Omron CX-Programmer project NuevoProyecto (CX-Programmer 9.50)

# PLC NewPLC1: CP1L-E EM

## Program P15 (cyclic task 0)
Local symbols
E 0.10 BOOL  ; Pulsador de Emergencia
Em 15.01 BOOL  ; Emergencia memorizada
Etapa_0 10.00 BOOL
Etapa_1 10.01 BOOL
Etapa_10 10.10 BOOL
Etapa_11 10.11 BOOL
Etapa_12 10.12 BOOL
Etapa_2 10.02 BOOL
Etapa_20 10.13 BOOL
Etapa_21 10.14 BOOL
Etapa_3 10.03 BOOL
Etapa_30 10.15 BOOL
Etapa_31 11.00 BOOL
Etapa_4 10.04 BOOL
Etapa_40 11.01 BOOL
Etapa_41 11.02 BOOL
Etapa_5 10.05 BOOL
Etapa_50 11.03 BOOL
Etapa_51 11.04 BOOL
Etapa_6 10.06 BOOL
Etapa_7 10.07 BOOL
Etapa_8 10.08 BOOL
Etapa_9 10.09 BOOL
FBS5 15.00 BOOL  ; Flanco Bajada S5
FC1 0.06 BOOL
FC2 0.07 BOOL
FC3 0.08 BOOL
FC4 0.09 BOOL
KC1 100.00 BOOL
KC2 100.01 BOOL
KC3 100.02 BOOL
KCP 100.03 BOOL
KCS 100.04 BOOL
KPD 100.05 BOOL
KPI 100.06 BOOL
R 0.11 BOOL  ; Pulsador de Rearme
S_1 0.01 BOOL
S_2 0.02 BOOL
S_3 0.03 BOOL
S_4 0.04 BOOL
S_5 0.05 BOOL
m 0.00 BOOL

### Section Sección1_GRAFCET_principal

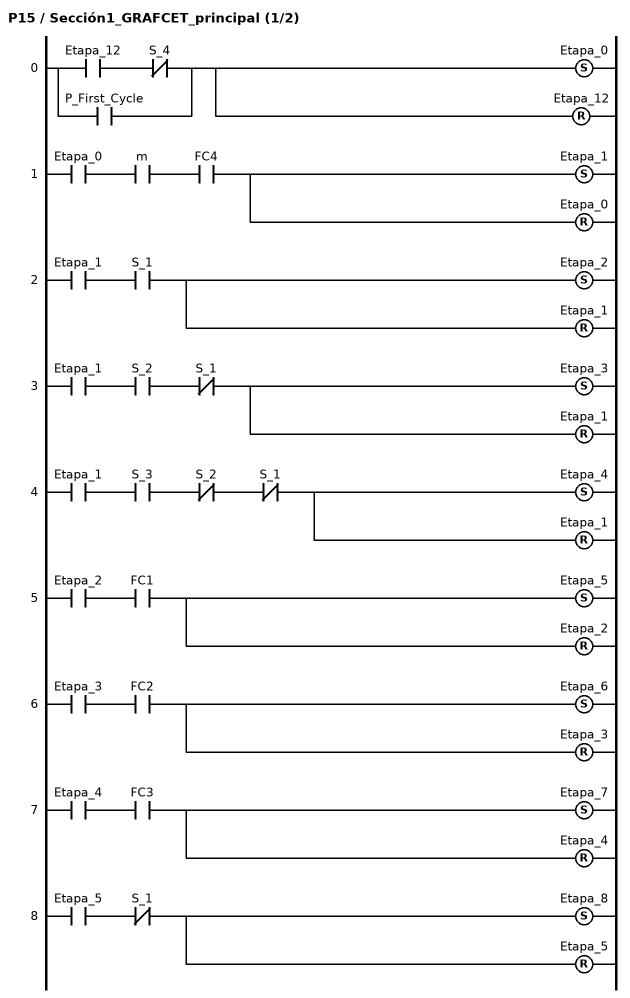
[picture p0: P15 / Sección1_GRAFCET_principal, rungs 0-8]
; rung 0
LD Etapa_12
ANDNOT S_4
OR P_First_Cycle
SET Etapa_0
RSET Etapa_12
; rung 1
LD Etapa_0
AND m
AND FC4
SET Etapa_1
RSET Etapa_0
; rung 2
LD Etapa_1
AND S_1
SET Etapa_2
RSET Etapa_1
; rung 3
LD Etapa_1
AND S_2
ANDNOT S_1
SET Etapa_3
RSET Etapa_1
; rung 4
LD Etapa_1
AND S_3
ANDNOT S_2
ANDNOT S_1
SET Etapa_4
RSET Etapa_1
; rung 5
LD Etapa_2
AND FC1
SET Etapa_5
RSET Etapa_2
; rung 6
LD Etapa_3
AND FC2
SET Etapa_6
RSET Etapa_3
; rung 7
LD Etapa_4
AND FC3
SET Etapa_7
RSET Etapa_4
; rung 8
LD Etapa_5
ANDNOT S_1
SET Etapa_8
RSET Etapa_5

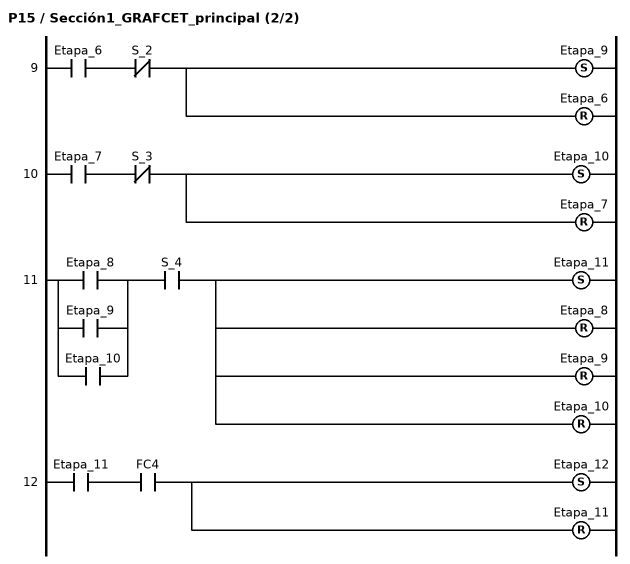
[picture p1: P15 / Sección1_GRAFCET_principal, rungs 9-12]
; rung 9
LD Etapa_6
ANDNOT S_2
SET Etapa_9
RSET Etapa_6
; rung 10
LD Etapa_7
ANDNOT S_3
SET Etapa_10
RSET Etapa_7
; rung 11
LD Etapa_8
OR Etapa_9
OR Etapa_10
AND S_4
SET Etapa_11
RSET Etapa_8
RSET Etapa_9
RSET Etapa_10
; rung 12
LD Etapa_11
AND FC4
SET Etapa_12
RSET Etapa_11

### Section Sección2_GRAFCET_CINTA1

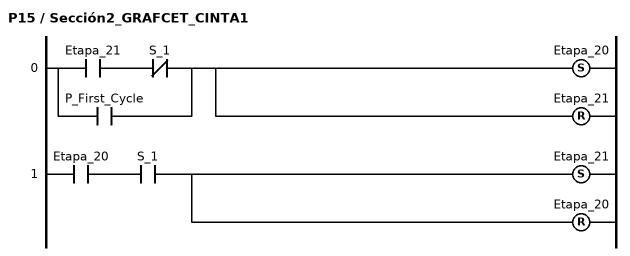
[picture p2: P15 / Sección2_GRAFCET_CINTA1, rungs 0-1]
; rung 0
LD Etapa_21
ANDNOT S_1
OR P_First_Cycle
SET Etapa_20
RSET Etapa_21
; rung 1
LD Etapa_20
AND S_1
SET Etapa_21
RSET Etapa_20

### Section Sección3_GRAFCET_CINTA2

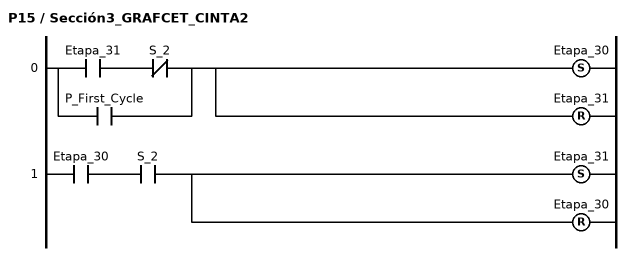
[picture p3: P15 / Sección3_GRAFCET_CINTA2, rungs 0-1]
; rung 0
LD Etapa_31
ANDNOT S_2
OR P_First_Cycle
SET Etapa_30
RSET Etapa_31
; rung 1
LD Etapa_30
AND S_2
SET Etapa_31
RSET Etapa_30

### Section Sección4_GRAFCET_CINTA3

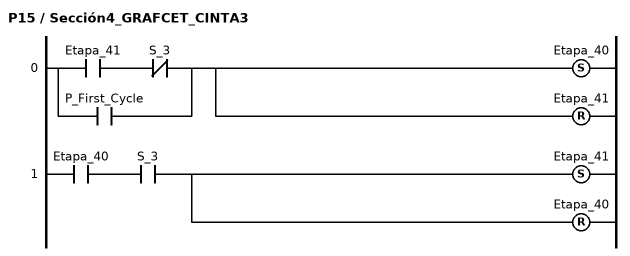
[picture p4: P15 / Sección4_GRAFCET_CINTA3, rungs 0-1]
; rung 0
LD Etapa_41
ANDNOT S_3
OR P_First_Cycle
SET Etapa_40
RSET Etapa_41
; rung 1
LD Etapa_40
AND S_3
SET Etapa_41
RSET Etapa_40

### Section Sección5_GRAFCET_CINTA_SALIDA

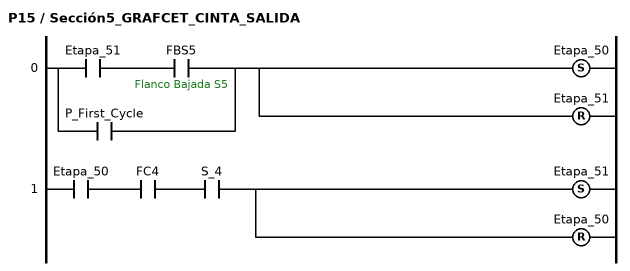
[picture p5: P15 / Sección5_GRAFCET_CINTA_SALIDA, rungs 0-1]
; rung 0
LD Etapa_51
AND FBS5  ; Flanco Bajada S5
OR P_First_Cycle
SET Etapa_50
RSET Etapa_51
; rung 1
LD Etapa_50
AND FC4
AND S_4
SET Etapa_51
RSET Etapa_50

### Section Sección6_Flanco_Bajada_S5

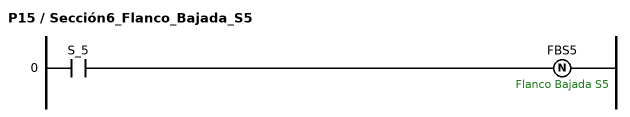
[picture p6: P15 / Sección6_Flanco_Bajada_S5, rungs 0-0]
; rung 0
LD S_5
DIFD(014) FBS5  ; Flanco Bajada S5

### Section Sección7_Emergencia_memorizada

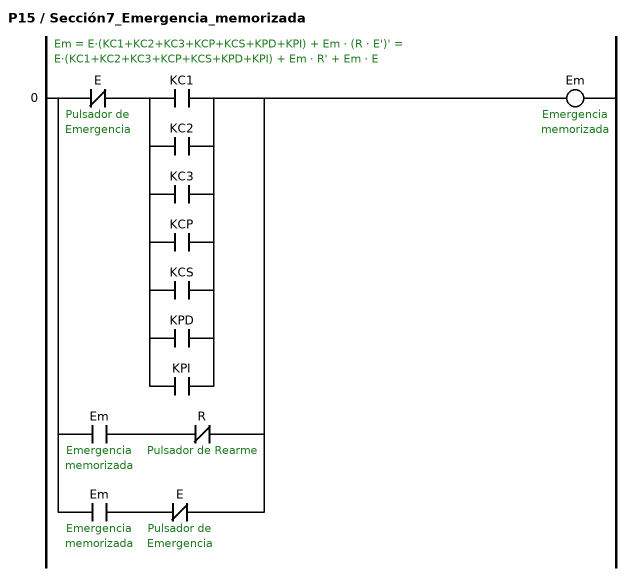
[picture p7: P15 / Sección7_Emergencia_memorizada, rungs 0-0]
; rung 0: Em = E·(KC1+KC2+KC3+KCP+KCS+KPD+KPI) + Em · (R · E')' = E·(KC1+KC2+KC3+KCP+KCS+KPD+KPI) + Em · R' + Em · E
LDNOT E  ; Pulsador de Emergencia  // E va negado por ser un CNC.
LD KC1
OR KC2
OR KC3
OR KCP
OR KCS
OR KPD
OR KPI
ANDLD
LD Em  ; Emergencia memorizada
ANDNOT R  ; Pulsador de Rearme
ORLD
LD Em  ; Emergencia memorizada
ANDNOT E  ; Pulsador de Emergencia  // E va negado por ser un CNC.
ORLD
OUT Em  ; Emergencia memorizada

### Section Sección8_Salidas

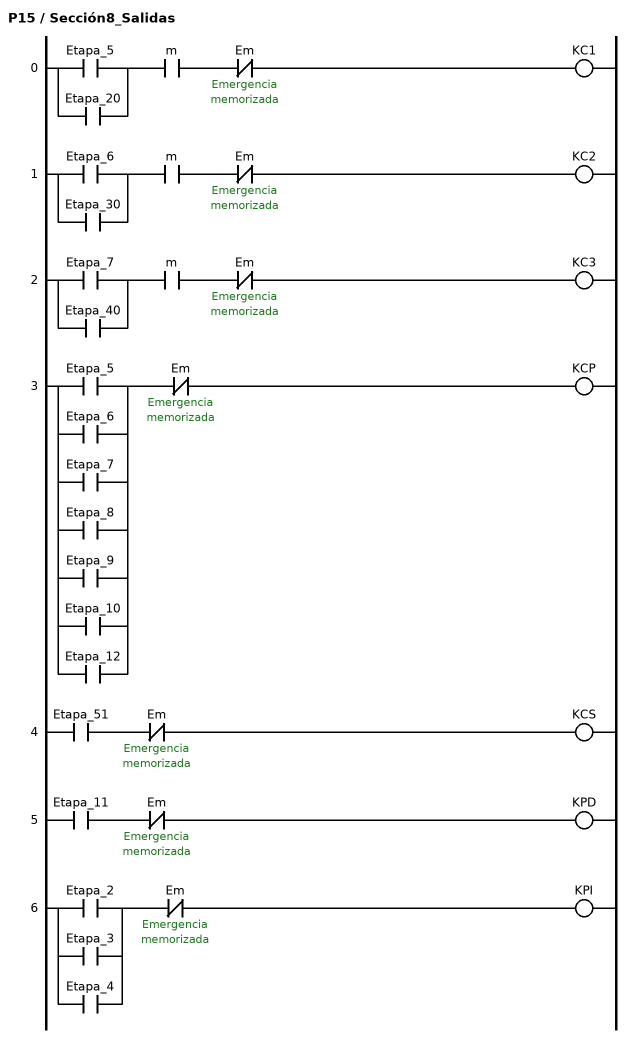
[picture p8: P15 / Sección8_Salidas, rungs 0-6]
; rung 0
LD Etapa_5
OR Etapa_20
AND m
ANDNOT Em  ; Emergencia memorizada
OUT KC1
; rung 1
LD Etapa_6
OR Etapa_30
AND m
ANDNOT Em  ; Emergencia memorizada
OUT KC2
; rung 2
LD Etapa_7
OR Etapa_40
AND m
ANDNOT Em  ; Emergencia memorizada
OUT KC3
; rung 3
LD Etapa_5
OR Etapa_6
OR Etapa_7
OR Etapa_8
OR Etapa_9
OR Etapa_10
OR Etapa_12
ANDNOT Em  ; Emergencia memorizada
OUT KCP
; rung 4
LD Etapa_51
ANDNOT Em  ; Emergencia memorizada
OUT KCS
; rung 5
LD Etapa_11
ANDNOT Em  ; Emergencia memorizada
OUT KPD
; rung 6
LD Etapa_2
OR Etapa_3
OR Etapa_4
ANDNOT Em  ; Emergencia memorizada
OUT KPI

### Section Sección9_END
; rung 0
END(001)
